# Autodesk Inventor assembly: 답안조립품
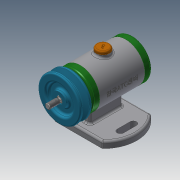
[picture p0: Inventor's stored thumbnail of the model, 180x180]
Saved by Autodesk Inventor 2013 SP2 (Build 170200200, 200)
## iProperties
Created: 2021-09
Part Number: 답안조립품
Document SubType Name: Assembly
Designer: kumcom13
Author: kumcom13
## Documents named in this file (14)
- C:\Users\kumcom13\Desktop\710906V1031\답안조립품.iam
- C:\Users\kumcom13\Desktop\710906V1031\본체.ipt
- C:\Users\kumcom13\Desktop\710906V1031\V벨트풀리.ipt
- C:\Users\kumcom13\Desktop\710906V1031\너트 M8.ipt
- C:\Users\kumcom13\Desktop\710906V1031\뒤커버.ipt
- C:\Users\kumcom13\Desktop\710906V1031\베어링 15x32x9.ipt
- C:\Users\kumcom13\Desktop\710906V1031\볼트 M4x12.ipt
- C:\Users\kumcom13\Desktop\710906V1031\스프링와셔 8.ipt
- C:\Users\kumcom13\Desktop\710906V1031\앞커버.ipt
- C:\Users\kumcom13\Desktop\710906V1031\오일 실 15x25x7.ipt
- C:\Users\kumcom13\Desktop\710906V1031\와셔 8x17.ipt
- C:\Users\kumcom13\Desktop\710906V1031\축.ipt
- C:\Users\kumcom13\Desktop\710906V1031\캡.ipt
- C:\Users\kumcom13\Desktop\710906V1031\키 3x3.ipt
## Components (1 placed, 1 different names)
1. V벨트풀리:1
